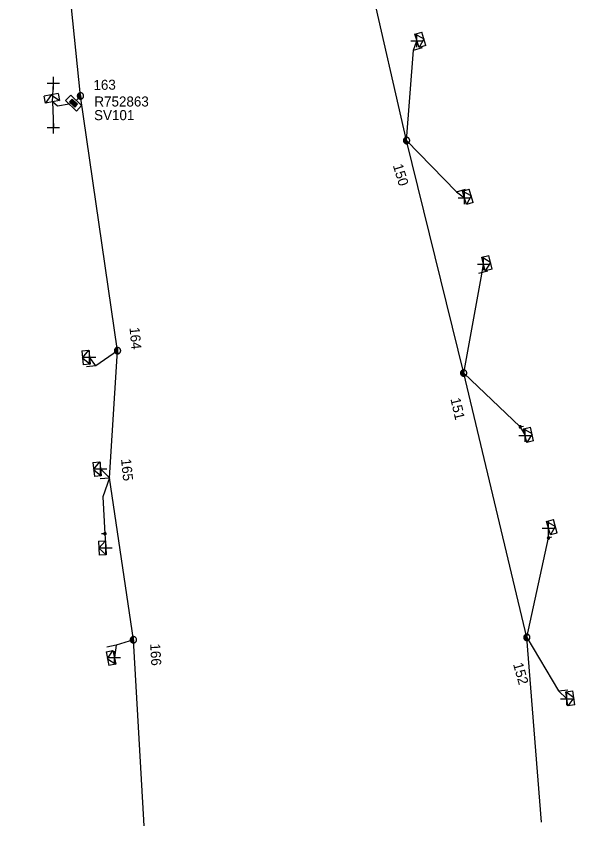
# Model space of a CAD drawing. Extents: x -544780 to -541582, y -1198995 to -1196551.
# Drawn here: x -542527.8 to -542472, y -1198994.5 to -1198913.7 of the extents above; entities that cross this region are included whole.
import ezdxf

# ---------------------------------------------------------------- set-up
doc = ezdxf.new("R2010")
doc.units = 0
for name, color, linetype in [('Vrstva 1', 7, 'Continuous'), ('Vrstva 13', 7, 'Continuous'), ('Vrstva 14', 7, 'Continuous'), ('Vrstva 2', 7, 'Continuous'), ('Vrstva 28', 7, 'Continuous'), ('Vrstva 29', 7, 'Continuous'), ('Vrstva 30', 7, 'Continuous'), ('Vrstva 31', 7, 'Continuous'), ('Vrstva 34', 7, 'Continuous'), ('Vrstva 5', 7, 'Continuous'), ('Vrstva 52', 7, 'Continuous'), ('Vrstva 54', 7, 'Continuous'), ('Vrstva 59', 7, 'Continuous'), ('Vrstva 8', 7, 'Continuous'), ('Vrstva 9', 7, 'Continuous')]:
    doc.layers.add(name, color=color, linetype=linetype)

# ---------------------------------------------------------------- blocks, each defined once
blk = doc.blocks.new('NN440')
at = {"layer": 'Vrstva 2'}
for points in [[(0.63, 0), (0.63, 0.06), (0.62, 0.13), (0.6, 0.19), (0.58, 0.25), (0.55, 0.31), (0.51, 0.37), (0.47, 0.42), (0.42, 0.46), (0.37, 0.51), (0.32, 0.54), (0.26, 0.57), (0.2, 0.59), (0.13, 0.61), (0.07, 0.62), (0, 0.63), (-0.06, 0.62), (-0.13, 0.61), (-0.19, 0.59), (-0.26, 0.57), (-0.31, 0.54), (-0.37, 0.51), (-0.42, 0.46), (-0.47, 0.42), (-0.51, 0.37), (-0.54, 0.31), (-0.57, 0.25), (-0.6, 0.19), (-0.62, 0.13), (-0.63, 0.06), (-0.63, 0), (-0.63, -0.07), (-0.62, -0.14), (-0.6, -0.2), (-0.57, -0.26), (-0.54, -0.32), (-0.51, -0.37), (-0.47, -0.43), (-0.42, -0.47), (-0.37, -0.51), (-0.31, -0.55), (-0.26, -0.58), (-0.19, -0.6), (-0.13, -0.62), (-0.06, -0.63), (0, -0.63), (0.07, -0.63), (0.13, -0.62), (0.2, -0.6), (0.26, -0.58), (0.32, -0.55), (0.37, -0.51), (0.42, -0.47), (0.47, -0.43), (0.51, -0.37), (0.55, -0.32), (0.58, -0.26), (0.6, -0.2), (0.62, -0.14), (0.63, -0.07), (0.63, 0)], [(-0.63, 0), (0.63, 0)], [(-0.6, -0.18), (0.57, -0.18)], [(-0.51, -0.32), (0.5, -0.32)], [(-0.37, -0.47), (0.35, -0.47)]]:
    blk.add_lwpolyline(points, dxfattribs=at)
blk = doc.blocks.new('NN800')
at = {"layer": 'Vrstva 1'}
for points in [[(-0.442, 0.442), (0.442, -0.442)], [(-0.442, -0.442), (0.442, 0.442)]]:
    blk.add_lwpolyline(points, dxfattribs=at)
blk = doc.blocks.new('NN620')
at = {"layer": 'Vrstva 8'}
for points in [[(0.752, 0.004), (-0.748, 0.004)], [(-0.748, 0.004), (-0.748, -0.746)], [(0.752, -0.746), (0.752, 0.004)], [(-0.748, -0.746), (0.752, -0.746)], [(0.368, -0.18), (-0.376, -0.18)], [(-0.376, -0.18), (-0.376, -0.558)], [(-0.376, -0.558), (0.368, -0.558)], [(0.321, -0.227), (-0.329, -0.227)], [(-0.329, -0.227), (-0.329, -0.51)], [(-0.329, -0.51), (0.321, -0.51)], [(0.274, -0.274), (-0.281, -0.274)], [(-0.281, -0.274), (-0.281, -0.463)], [(-0.281, -0.463), (0.274, -0.463)], [(0.227, -0.321), (-0.234, -0.321)], [(-0.234, -0.321), (-0.234, -0.416)], [(-0.234, -0.416), (0.227, -0.416)], [(-0.193, -0.369), (0.185, -0.369)], [(0.227, -0.416), (0.227, -0.321)], [(0.274, -0.463), (0.274, -0.274)], [(0.321, -0.51), (0.321, -0.227)], [(0.368, -0.558), (0.368, -0.18)]]:
    blk.add_lwpolyline(points, dxfattribs=at)
blk = doc.blocks.new('NN630')
at = {"layer": 'Vrstva 9'}
for points in [[(-0.003, -0.7), (-0.703, 0)], [(-0.703, -0.7), (-0.703, 0), (0.697, 0), (0.697, -0.7)], [(-0.703, -0.7), (0.697, -0.7)], [(-0.003, -0.7), (0.697, 0)]]:
    blk.add_lwpolyline(points, dxfattribs=at)
blk = doc.blocks.new('NN500')
at = {"layer": 'Vrstva 2'}
for points in [[(0, -0.24), (0.02, -0.23), (0.05, -0.23), (0.07, -0.22), (0.09, -0.22), (0.12, -0.2), (0.14, -0.19), (0.16, -0.18), (0.17, -0.16), (0.19, -0.14), (0.2, -0.12), (0.21, -0.1), (0.22, -0.07), (0.23, -0.05), (0.23, -0.02), (0.23, 0), (0.23, 0.02), (0.23, 0.05), (0.22, 0.07), (0.21, 0.1), (0.2, 0.12), (0.19, 0.14), (0.17, 0.16), (0.16, 0.17), (0.14, 0.19), (0.12, 0.2), (0.09, 0.21), (0.07, 0.22), (0.05, 0.23), (0.02, 0.23), (0, 0.23), (-0.03, 0.23), (-0.05, 0.23), (-0.07, 0.22), (-0.1, 0.21), (-0.12, 0.2), (-0.14, 0.19), (-0.16, 0.17), (-0.18, 0.16), (-0.19, 0.14), (-0.2, 0.12), (-0.22, 0.1), (-0.22, 0.07), (-0.23, 0.05), (-0.23, 0.02), (-0.24, 0), (-0.23, -0.02), (-0.23, -0.05), (-0.22, -0.07), (-0.22, -0.1), (-0.2, -0.12), (-0.19, -0.14), (-0.18, -0.16), (-0.16, -0.18), (-0.14, -0.19), (-0.12, -0.2), (-0.1, -0.22), (-0.07, -0.22), (-0.05, -0.23), (-0.03, -0.23), (0, -0.24)], [(0, -0.24), (0.02, -0.23), (0.05, -0.23), (0.07, -0.22), (0.09, -0.22), (0.12, -0.2), (0.14, -0.19), (0.16, -0.18), (0.17, -0.16), (0.19, -0.14), (0.2, -0.12), (0.21, -0.1), (0.22, -0.07), (0.23, -0.05), (0.23, -0.02), (0.23, 0), (0.23, 0.02), (0.23, 0.05), (0.22, 0.07), (0.21, 0.1), (0.2, 0.12), (0.19, 0.14), (0.17, 0.16), (0.16, 0.17), (0.14, 0.19), (0.12, 0.2), (0.09, 0.21), (0.07, 0.22), (0.05, 0.23), (0.02, 0.23), (0, 0.23), (-0.03, 0.23), (-0.05, 0.23), (-0.07, 0.22), (-0.1, 0.21), (-0.12, 0.2), (-0.14, 0.19), (-0.16, 0.17), (-0.18, 0.16), (-0.19, 0.14), (-0.2, 0.12), (-0.22, 0.1), (-0.22, 0.07), (-0.23, 0.05), (-0.23, 0.02), (-0.24, 0), (-0.23, -0.02), (-0.23, -0.05), (-0.22, -0.07), (-0.22, -0.1), (-0.2, -0.12), (-0.19, -0.14), (-0.18, -0.16), (-0.16, -0.18), (-0.14, -0.19), (-0.12, -0.2), (-0.1, -0.22), (-0.07, -0.22), (-0.05, -0.23), (-0.03, -0.23), (0, -0.24)], [(0, -0.21), (0.02, -0.2), (0.04, -0.2), (0.06, -0.2), (0.08, -0.19), (0.1, -0.18), (0.12, -0.17), (0.14, -0.15), (0.15, -0.14), (0.16, -0.12), (0.18, -0.1), (0.19, -0.08), (0.19, -0.06), (0.2, -0.04), (0.2, -0.02), (0.2, 0), (0.2, 0.02), (0.2, 0.04), (0.19, 0.06), (0.19, 0.08), (0.18, 0.1), (0.16, 0.12), (0.15, 0.14), (0.14, 0.15), (0.12, 0.17), (0.1, 0.18), (0.08, 0.19), (0.06, 0.19), (0.04, 0.2), (0.02, 0.2), (0, 0.2), (-0.02, 0.2), (-0.04, 0.2), (-0.06, 0.19), (-0.08, 0.19), (-0.1, 0.18), (-0.12, 0.17), (-0.14, 0.15), (-0.15, 0.14), (-0.17, 0.12), (-0.18, 0.1), (-0.19, 0.08), (-0.2, 0.06), (-0.2, 0.04), (-0.21, 0.02), (-0.21, 0), (-0.21, -0.02), (-0.2, -0.04), (-0.2, -0.06), (-0.19, -0.08), (-0.18, -0.1), (-0.17, -0.12), (-0.15, -0.14), (-0.14, -0.15), (-0.12, -0.17), (-0.1, -0.18), (-0.08, -0.19), (-0.06, -0.2), (-0.04, -0.2), (-0.02, -0.2), (0, -0.21)], [(0, -0.18), (0.02, -0.18), (0.04, -0.17), (0.05, -0.17), (0.07, -0.16), (0.09, -0.15), (0.1, -0.14), (0.12, -0.13), (0.13, -0.12), (0.14, -0.1), (0.15, -0.09), (0.16, -0.07), (0.17, -0.05), (0.17, -0.04), (0.17, -0.02), (0.17, 0), (0.17, 0.02), (0.17, 0.04), (0.17, 0.05), (0.16, 0.07), (0.15, 0.09), (0.14, 0.1), (0.13, 0.12), (0.12, 0.13), (0.1, 0.14), (0.09, 0.15), (0.07, 0.16), (0.05, 0.17), (0.04, 0.17), (0.02, 0.17), (0, 0.18), (-0.02, 0.17), (-0.04, 0.17), (-0.06, 0.17), (-0.07, 0.16), (-0.09, 0.15), (-0.1, 0.14), (-0.12, 0.13), (-0.13, 0.12), (-0.14, 0.1), (-0.15, 0.09), (-0.16, 0.07), (-0.17, 0.05), (-0.17, 0.04), (-0.18, 0.02), (-0.18, 0), (-0.18, -0.02), (-0.17, -0.04), (-0.17, -0.05), (-0.16, -0.07), (-0.15, -0.09), (-0.14, -0.1), (-0.13, -0.12), (-0.12, -0.13), (-0.1, -0.14), (-0.09, -0.15), (-0.07, -0.16), (-0.06, -0.17), (-0.04, -0.17), (-0.02, -0.18), (0, -0.18)], [(0, -0.15), (0.01, -0.15), (0.03, -0.14), (0.04, -0.14), (0.06, -0.13), (0.07, -0.13), (0.08, -0.12), (0.1, -0.11), (0.11, -0.1), (0.12, -0.09), (0.13, -0.07), (0.13, -0.06), (0.14, -0.05), (0.14, -0.03), (0.14, -0.02), (0.14, 0), (0.14, 0.01), (0.14, 0.03), (0.14, 0.04), (0.13, 0.06), (0.13, 0.07), (0.12, 0.09), (0.11, 0.1), (0.1, 0.11), (0.08, 0.12), (0.07, 0.13), (0.06, 0.13), (0.04, 0.14), (0.03, 0.14), (0.01, 0.14), (0, 0.15), (-0.02, 0.14), (-0.03, 0.14), (-0.05, 0.14), (-0.06, 0.13), (-0.07, 0.13), (-0.09, 0.12), (-0.1, 0.11), (-0.11, 0.1), (-0.12, 0.09), (-0.13, 0.07), (-0.13, 0.06), (-0.14, 0.04), (-0.14, 0.03), (-0.15, 0.01), (-0.15, 0), (-0.15, -0.02), (-0.14, -0.03), (-0.14, -0.05), (-0.13, -0.06), (-0.13, -0.07), (-0.12, -0.09), (-0.11, -0.1), (-0.1, -0.11), (-0.09, -0.12), (-0.07, -0.13), (-0.06, -0.13), (-0.05, -0.14), (-0.03, -0.14), (-0.02, -0.15), (0, -0.15)], [(0, -0.12), (0.01, -0.12), (0.02, -0.11), (0.03, -0.11), (0.05, -0.11), (0.06, -0.1), (0.07, -0.09), (0.08, -0.09), (0.09, -0.08), (0.09, -0.07), (0.1, -0.06), (0.11, -0.05), (0.11, -0.04), (0.11, -0.02), (0.11, -0.01), (0.12, 0), (0.11, 0.01), (0.11, 0.02), (0.11, 0.04), (0.11, 0.05), (0.1, 0.06), (0.09, 0.07), (0.09, 0.08), (0.08, 0.09), (0.07, 0.09), (0.06, 0.1), (0.05, 0.11), (0.03, 0.11), (0.02, 0.11), (0.01, 0.12), (0, 0.12), (-0.01, 0.12), (-0.03, 0.11), (-0.04, 0.11), (-0.05, 0.11), (-0.06, 0.1), (-0.07, 0.09), (-0.08, 0.09), (-0.09, 0.08), (-0.1, 0.07), (-0.1, 0.06), (-0.11, 0.05), (-0.11, 0.04), (-0.12, 0.02), (-0.12, 0.01), (-0.12, 0), (-0.12, -0.01), (-0.12, -0.02), (-0.11, -0.04), (-0.11, -0.05), (-0.1, -0.06), (-0.1, -0.07), (-0.09, -0.08), (-0.08, -0.09), (-0.07, -0.09), (-0.06, -0.1), (-0.05, -0.11), (-0.04, -0.11), (-0.03, -0.11), (-0.01, -0.12), (0, -0.12)], [(0, -0.09), (0.01, -0.09), (0.02, -0.09), (0.03, -0.08), (0.03, -0.08), (0.04, -0.08), (0.05, -0.07), (0.06, -0.07), (0.06, -0.06), (0.07, -0.05), (0.07, -0.04), (0.08, -0.04), (0.08, -0.03), (0.08, -0.02), (0.09, -0.01), (0.09, 0), (0.09, 0.01), (0.08, 0.02), (0.08, 0.03), (0.08, 0.03), (0.07, 0.04), (0.07, 0.05), (0.06, 0.06), (0.06, 0.06), (0.05, 0.07), (0.04, 0.07), (0.03, 0.08), (0.03, 0.08), (0.02, 0.08), (0.01, 0.09), (0, 0.09), (-0.01, 0.09), (-0.02, 0.08), (-0.03, 0.08), (-0.04, 0.08), (-0.04, 0.07), (-0.05, 0.07), (-0.06, 0.06), (-0.07, 0.06), (-0.07, 0.05), (-0.08, 0.04), (-0.08, 0.03), (-0.08, 0.03), (-0.09, 0.02), (-0.09, 0.01), (-0.09, 0), (-0.09, -0.01), (-0.09, -0.02), (-0.08, -0.03), (-0.08, -0.04), (-0.08, -0.04), (-0.07, -0.05), (-0.07, -0.06), (-0.06, -0.07), (-0.05, -0.07), (-0.04, -0.08), (-0.04, -0.08), (-0.03, -0.08), (-0.02, -0.09), (-0.01, -0.09), (0, -0.09)], [(0, -0.06), (0, -0.06), (0.01, -0.06), (0.02, -0.05), (0.02, -0.05), (0.03, -0.05), (0.03, -0.05), (0.04, -0.04), (0.04, -0.04), (0.05, -0.03), (0.05, -0.03), (0.05, -0.02), (0.05, -0.02), (0.05, -0.01), (0.06, -0.01), (0.06, 0), (0.06, 0.01), (0.05, 0.01), (0.05, 0.02), (0.05, 0.02), (0.05, 0.03), (0.05, 0.03), (0.04, 0.04), (0.04, 0.04), (0.03, 0.05), (0.03, 0.05), (0.02, 0.05), (0.02, 0.05), (0.01, 0.06), (0, 0.06), (0, 0.06), (-0.01, 0.06), (-0.01, 0.06), (-0.02, 0.05), (-0.02, 0.05), (-0.03, 0.05), (-0.03, 0.05), (-0.04, 0.04), (-0.04, 0.04), (-0.05, 0.03), (-0.05, 0.03), (-0.05, 0.02), (-0.06, 0.02), (-0.06, 0.01), (-0.06, 0.01), (-0.06, 0), (-0.06, -0.01), (-0.06, -0.01), (-0.06, -0.02), (-0.05, -0.02), (-0.05, -0.03), (-0.05, -0.03), (-0.04, -0.04), (-0.04, -0.04), (-0.03, -0.05), (-0.03, -0.05), (-0.02, -0.05), (-0.02, -0.05), (-0.01, -0.06), (-0.01, -0.06), (0, -0.06)], [(0, -0.03), (0, -0.03), (0, -0.03), (0.01, -0.03), (0.01, -0.03), (0.01, -0.02), (0.02, -0.02), (0.02, -0.02), (0.02, -0.02), (0.02, -0.02), (0.02, -0.01), (0.02, -0.01), (0.03, -0.01), (0.03, -0.01), (0.03, 0), (0.03, 0), (0.03, 0), (0.03, 0.01), (0.03, 0.01), (0.02, 0.01), (0.02, 0.01), (0.02, 0.02), (0.02, 0.02), (0.02, 0.02), (0.02, 0.02), (0.01, 0.02), (0.01, 0.02), (0.01, 0.03), (0, 0.03), (0, 0.03), (0, 0.03), (0, 0.03), (-0.01, 0.03), (-0.01, 0.03), (-0.01, 0.02), (-0.02, 0.02), (-0.02, 0.02), (-0.02, 0.02), (-0.02, 0.02), (-0.02, 0.02), (-0.03, 0.01), (-0.03, 0.01), (-0.03, 0.01), (-0.03, 0.01), (-0.03, 0), (-0.03, 0), (-0.03, 0), (-0.03, -0.01), (-0.03, -0.01), (-0.03, -0.01), (-0.03, -0.01), (-0.02, -0.02), (-0.02, -0.02), (-0.02, -0.02), (-0.02, -0.02), (-0.02, -0.02), (-0.01, -0.03), (-0.01, -0.03), (-0.01, -0.03), (0, -0.03), (0, -0.03)], [(0.23, 0), (0.7, 0)]]:
    blk.add_lwpolyline(points, dxfattribs=at)
blk = doc.blocks.new('NN510')
at = {"layer": 'Vrstva 2'}
blk.add_lwpolyline([(0.001, 0.002), (0.001, 0.939)], dxfattribs=at)

msp = doc.modelspace()

# ---------------------------------------------------------------- linework, layer by layer
at = {"layer": 'Vrstva 1'}
for points in [[(-542475.347, -1198994.15), (-542476.818, -1198975.71), (-542483.119, -1198949.335), (-542488.815, -1198926.134), (-542495.947, -1198894.974), (-542502.711, -1198869.077), (-542502.843, -1198868.609)], [(-542521.346, -1198921.686), (-542524.075, -1198894.957), (-542527.76, -1198872.552)], [(-542515.006, -1198994.506), (-542516.064, -1198975.946), (-542518.438, -1198959.805), (-542517.648, -1198947.103), (-542521.346, -1198921.686)]]:
    msp.add_lwpolyline(points, dxfattribs=at)
at = {"layer": 'Vrstva 5'}
msp.add_lwpolyline([(-542521.346, -1198921.686), (-542521.782, -1198922.135)], dxfattribs=at)
at = {"layer": 'Vrstva 52'}
msp.add_lwpolyline([(-542522.373, -1198922.495), (-542522.468, -1198922.512), (-542523.642, -1198922.704), (-542524.145, -1198922.274)], dxfattribs=at)
at = {"layer": 'Vrstva 54'}
for points in [[(-542488.815, -1198926.134), (-542483.848, -1198931.246), (-542483.049, -1198931.855)], [(-542483.119, -1198949.335), (-542481.32, -1198939.47), (-542481.131, -1198938.456)], [(-542517.648, -1198947.103), (-542519.807, -1198948.619), (-542520.453, -1198947.74)], [(-542483.119, -1198949.335), (-542477.481, -1198954.7), (-542476.984, -1198955.565)], [(-542476.818, -1198975.71), (-542474.659, -1198965.779), (-542474.655, -1198964.815)], [(-542476.818, -1198975.71), (-542473.646, -1198981.053), (-542472.824, -1198981.837)], [(-542516.064, -1198975.946), (-542517.781, -1198976.493), (-542517.969, -1198977.701)]]:
    msp.add_lwpolyline(points, dxfattribs=at)
at = {"layer": 'Vrstva 59'}
for points in [[(-542524.145, -1198922.274), (-542524.049, -1198920.419)], [(-542524.145, -1198922.274), (-542524.049, -1198924.824)]]:
    msp.add_lwpolyline(points, dxfattribs=at)
at = {"layer": 'Vrstva 8'}
for points in [[(-542488.815, -1198926.134), (-542488.117, -1198917.13), (-542487.778, -1198916.18)], [(-542518.438, -1198959.805), (-542519.338, -1198958.883)], [(-542518.438, -1198959.805), (-542519.102, -1198961.693), (-542518.902, -1198965.364), (-542518.827, -1198966.771)]]:
    msp.add_lwpolyline(points, dxfattribs=at)

# ---------------------------------------------------------------- block references
at = {"layer": 'Vrstva 13'}
for p, rotation in [((-542488.118, -1198917.13), -73.32813607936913), ((-542483.849, -1198931.246), -73.06673328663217), ((-542481.606, -1198939.353), -75.95232223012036), ((-542519.806, -1198948.62), 95.45245561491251), ((-542518.437, -1198959.806), 95.83743335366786), ((-542517.781, -1198976.493), 101.50773058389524), ((-542473.646, -1198981.052), -82.07630274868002)]:
    msp.add_blockref('NN510', p, dxfattribs=dict(at, rotation=rotation))
for name, p, xscale, yscale, rotation in [('NN440', (-542521.347, -1198921.687), 0.5000000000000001, 0.5, -79.24510005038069), ('NN440', (-542488.815, -1198926.134), 0.5, 0.5, -73.0667333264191), ('NN440', (-542517.649, -1198947.103), 0.49999999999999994, 0.5, -84.54754445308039), ('NN440', (-542483.12, -1198949.335), 0.5, 0.5, -76.98871385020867), ('NN500', (-542477.481, -1198954.7), 0.49999999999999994, 0.5000000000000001, 13.010999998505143), ('NN500', (-542518.902, -1198965.364), 0.5, 0.5000000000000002, -176.8970000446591), ('NN500', (-542474.659, -1198965.779), 0.5, 0.5, 15.795999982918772), ('NN440', (-542516.064, -1198975.946), 0.49999999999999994, 0.4999999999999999, -86.89686659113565), ('NN440', (-542476.819, -1198975.711), 0.5, 0.49999999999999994, -74.20380834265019)]:
    msp.add_blockref(name, p, dxfattribs=dict(at, xscale=xscale, yscale=yscale, rotation=rotation))
at = {"layer": 'Vrstva 28', "rotation": -44.02933692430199}
msp.add_blockref('NN620', (-542521.782, -1198922.135), dxfattribs=at)
at = {"layer": 'Vrstva 31'}
for p, rotation in [((-542487.778, -1198916.18), 106.67186392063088), ((-542524.145, -1198922.274), -169.2451861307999), ((-542483.049, -1198931.855), 106.93326667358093), ((-542481.131, -1198938.456), 104.04767776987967), ((-542520.453, -1198947.74), -84.54754444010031), ((-542476.984, -1198955.565), 103.01128608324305), ((-542519.338, -1198958.883), -84.1625666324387), ((-542474.655, -1198964.815), 105.79619165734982), ((-542518.827, -1198966.771), -86.89686665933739), ((-542517.969, -1198977.701), -78.49226948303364), ((-542472.824, -1198981.837), 97.92369718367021)]:
    msp.add_blockref('NN630', p, dxfattribs=dict(at, rotation=rotation))
at = {"layer": 'Vrstva 34'}
for p, rotation in [((-542487.778, -1198916.18), 45), ((-542524.049, -1198920.419), 45), ((-542524.049, -1198924.824), 45), ((-542483.049, -1198931.855), 45), ((-542481.131, -1198938.456), 45), ((-542520.453, -1198947.74), 45), ((-542476.984, -1198955.565), 45.00000009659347), ((-542519.338, -1198958.883), 45), ((-542474.655, -1198964.815), 45.00000009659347), ((-542518.827, -1198966.771), 45.00000009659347), ((-542517.969, -1198977.701), 45), ((-542472.824, -1198981.837), 45)]:
    msp.add_blockref('NN800', p, dxfattribs=dict(at, rotation=rotation))

# ---------------------------------------------------------------- texts
at = {"layer": 'Vrstva 14'}
for s, rotation, p in [('163', 1.059, (-542520.046, -1198921.098)), ('150', 286.933, (-542490.195, -1198928.629)), ('164', 275.452, (-542516.46, -1198944.801)), ('151', 283.011, (-542484.448, -1198951.917)), ('165', 275.837, (-542517.308, -1198957.928)), ('166', 273.103, (-542514.396, -1198976.334)), ('152', 285.796, (-542478.202, -1198978.376))]:
    msp.add_text(s, height=1, rotation=rotation, dxfattribs=at).set_placement(p)
at = {"layer": 'Vrstva 29'}
msp.add_text('R752863', height=1, dxfattribs=at).set_placement((-542519.96, -1198922.741))
at = {"layer": 'Vrstva 30'}
msp.add_text('SV101', height=1, dxfattribs=at).set_placement((-542519.988, -1198924.104))

doc.saveas('drawing.dxf')
